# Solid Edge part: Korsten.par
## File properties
Author: Egon 815
Template: Normal.par
Last saved by: Egon 815
Revision: 5
Application: Solid Edge
Accuracy: 0,990
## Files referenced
..\Laev.asm
.C:\Kool\3D Modelleerimine\LaevaJoonis\Laev.asm
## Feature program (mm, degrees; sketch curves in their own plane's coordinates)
sketch for "unnamed Protrusion 1" plane through (0, 0, 8310) normal (0, 0, 1) x-axis (1, 0, 0)
  line (2766.1847, 955.2363) -> (2766.1847, -1432.5005)
  arc centre (854.3232, -1432.5005) radius 1911.8614 from (854.3232, -3344.362) to (2766.1847, -1432.5005) ccw
  line (854.3232, -3344.362) -> (-854.3232, -3344.362)
  arc centre (-854.3232, -1432.5005) radius 1911.8614 from (-2766.1847, -1432.5005) to (-854.3232, -3344.362) ccw
  line (-2766.1847, 955.2363) -> (-2766.1847, -1432.5005)
  arc centre (-854.3232, 955.2363) radius 1911.8614 from (-2766.1847, 955.2363) to (-854.3232, 2867.0978) cw
  line (-854.3232, 2867.0978) -> (854.3232, 2867.0978)
  arc centre (854.3232, 955.2363) radius 1911.8614 from (854.3232, 2867.0978) to (2766.1847, 955.2363) cw
extrude "unnamed Protrusion 1" add to key point along +normal
thinwall "unnamed Thinwall 1"
sketch for "unnamed Protrusion 2" plane through (0, -238.6321, 8310) normal (0, 0, -1) x-axis (0, 1, 0)
  line (238.6321, 6229.7809) -> (5327.3209, 6229.7809)
  line (5327.3209, 6229.7809) -> (5327.3209, -6074.0882)
  line (5327.3209, -6074.0882) -> (238.6321, -6074.0882)
  line (238.6321, -6074.0882) -> (238.6321, 6229.7809)
extrude "unnamed Protrusion 2" add to key point along -normal
sketch for "unnamed Protrusion 3" plane through (55.1803, 2544.3444, 11688.7578) normal (0, 0, 1) x-axis (0, 1, 0)
  line (-3976.8449, -4119.118) -> (911.1739, -4119.118)
  line (911.1739, -4119.118) -> (911.1739, 55.1803)
  line (911.1739, 4229.4786) -> (911.1739, 55.1803)
  line (-3976.8449, 4229.4786) -> (911.1739, 4229.4786)
  line (-3976.8449, 4229.4786) -> (-3976.8449, 55.1803)
  line (-3976.8449, -4119.118) -> (-3976.8449, 55.1803)
extrude "unnamed Protrusion 3" add to key point along +normal
chamfer "Chamfer_5" setback 200
fillet "Round_1" radius 1000
fillet "Round_3" radius 2000
fillet "Round_4" radius 1000
fillet "Round_5" radius 1000
sketch for "unnamed Protrusion 4" plane through (77.8463, 872.1634, 8310) normal (0, 0, -1) x-axis (1, 0, 0)
  line (-9245.1108, 5692.4091) -> (-6151.9346, 872.1634)
  line (-9245.1108, 5692.4091) -> (-77.8463, 5692.4091)
  line (9089.4181, 5692.4091) -> (-77.8463, 5692.4091)
  line (9089.4181, 5692.4091) -> (5996.2419, 872.1634)
  line (5996.2419, 872.1634) -> (-155.6927, 872.1634)
extrude "unnamed Protrusion 4" add to key point along -normal
fillet "Round_6" radius 500
chamfer "Chamfer_7" setback 200
chamfer "Chamfer_10" setback 200
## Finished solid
Body 1: solid body, 78 faces, 196 edges, 121 vertices.
  Faces by surface: plane 52, cylinder 18, torus 6, blend 2
  Edges by curve: line 140, circle 42, intersection 10, ellipse 4
Bounding box of the edges (mm; curved faces can reach further): 18334.529 x 9908.934 x 15550.165, from (-9167.2645, -4820.2457, 8310) to (9167.2645, 5088.6888, 23860.165).
Cylindrical faces by radius (mm): R500 x1, R1000 x7, R1851.8614 x4, R1911.8614 x4, R2000 x2
Toroidal faces (ring radius, tube radius in mm): R2411.8614 r500 x2, R2911.8614 r1000 x4
Planar faces by outward normal: +x 6, +y 4, +z 7, -x 6, -y 7, -z 4, oblique 18
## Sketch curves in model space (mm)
line (6074.0882, 0, 8310) -> (-77.8463, 0, 8310)
line (9167.2645, -4820.2457, 8310) -> (6074.0882, 0, 8310)
line (9167.2645, -4820.2457, 8310) -> (0, -4820.2457, 8310)
line (-9167.2645, -4820.2457, 8310) -> (0, -4820.2457, 8310)
line (-9167.2645, -4820.2457, 8310) -> (-6074.0882, 0, 8310)
line (-6074.0882, 0, 8310) -> (77.8463, 0, 8310)
line (-4174.2983, 3455.5183, 11688.7578) -> (0, 3455.5183, 11688.7578)
line (4174.2983, 3455.5183, 11688.7578) -> (0, 3455.5183, 11688.7578)
line (4174.2983, -1432.5005, 11688.7578) -> (4174.2983, 3455.5183, 11688.7578)
line (4174.2983, -1432.5005, 11688.7578) -> (0, -1432.5005, 11688.7578)
line (-4174.2983, -1432.5005, 11688.7578) -> (0, -1432.5005, 11688.7578)
line (-4174.2983, -1432.5005, 11688.7578) -> (-4174.2983, 3455.5183, 11688.7578)
line (6229.7809, 0, 8310) -> (6229.7809, 5088.6888, 8310)
line (6229.7809, 5088.6888, 8310) -> (-6074.0882, 5088.6888, 8310)
line (-6074.0882, 5088.6888, 8310) -> (-6074.0882, 0, 8310)
line (-6074.0882, 0, 8310) -> (6229.7809, 0, 8310)
line (-2766.1847, 955.2363, 8310) -> (-2766.1847, -1432.5005, 8310)
line (854.3232, -3344.362, 8310) -> (-854.3232, -3344.362, 8310)
line (-854.3232, 2867.0978, 8310) -> (854.3232, 2867.0978, 8310)
line (2766.1847, 955.2363, 8310) -> (2766.1847, -1432.5005, 8310)
arc centre (-854.3232, 955.2363, 8310) radius 1911.8614 from (-2766.1847, 955.2363, 8310) through (-2166.3221, 2345.8739, 8310) to (-854.3232, 2867.0978, 8310)
arc centre (854.3232, 955.2363, 8310) radius 1911.8614 from (854.3232, 2867.0978, 8310) through (2244.9608, 2267.2352, 8310) to (2766.1847, 955.2363, 8310)
arc centre (854.3232, -1432.5005, 8310) radius 1911.8614 from (854.3232, -3344.362, 8310) through (2244.9608, -2744.4995, 8310) to (2766.1847, -1432.5005, 8310)
arc centre (-854.3232, -1432.5005, 8310) radius 1911.8614 from (-2766.1847, -1432.5005, 8310) through (-2166.3221, -2823.1382, 8310) to (-854.3232, -3344.362, 8310)
line (-2766.1847, 955.2363, 8310) -> (-2766.1847, -1432.5005, 8310)
line (854.3232, -3344.362, 8310) -> (-854.3232, -3344.362, 8310)
line (-854.3232, 2867.0978, 8310) -> (854.3232, 2867.0978, 8310)
line (2766.1847, 955.2363, 8310) -> (2766.1847, -1432.5005, 8310)
arc centre (-854.3232, 955.2363, 8310) radius 1911.8614 from (-2766.1847, 955.2363, 8310) through (-2166.3221, 2345.8739, 8310) to (-854.3232, 2867.0978, 8310)
arc centre (854.3232, 955.2363, 8310) radius 1911.8614 from (854.3232, 2867.0978, 8310) through (2244.9608, 2267.2352, 8310) to (2766.1847, 955.2363, 8310)
arc centre (854.3232, -1432.5005, 8310) radius 1911.8614 from (854.3232, -3344.362, 8310) through (2244.9608, -2744.4995, 8310) to (2766.1847, -1432.5005, 8310)
arc centre (-854.3232, -1432.5005, 8310) radius 1911.8614 from (-2766.1847, -1432.5005, 8310) through (-2166.3221, -2823.1382, 8310) to (-854.3232, -3344.362, 8310)
line (-2893.7083, 1010.2748, 8310) -> (-2893.7083, -1487.539, 8310)
line (893.7083, -3487.539, 8310) -> (-893.7083, -3487.539, 8310)
line (-893.7083, 3010.2748, 8310) -> (893.7083, 3010.2748, 8310)
line (2893.7083, 1010.2748, 8310) -> (2893.7083, -1487.539, 8310)
arc centre (-893.7083, 1010.2748, 8310) radius 2000 from (-2893.7083, 1010.2748, 8310) through (-2266.1916, 2465.022, 8310) to (-893.7083, 3010.2748, 8310)
arc centre (893.7083, 1010.2748, 8310) radius 2000 from (893.7083, 3010.2748, 8310) through (2348.4556, 2382.758, 8310) to (2893.7083, 1010.2748, 8310)
arc centre (893.7083, -1487.539, 8310) radius 2000 from (893.7083, -3487.539, 8310) through (2348.4556, -2860.0223, 8310) to (2893.7083, -1487.539, 8310)
arc centre (-893.7083, -1487.539, 8310) radius 2000 from (-2893.7083, -1487.539, 8310) through (-2266.1916, -2942.2863, 8310) to (-893.7083, -3487.539, 8310)
line (-2893.7083, 1010.2748, 8310) -> (-2893.7083, -1487.539, 8310)
line (893.7083, -3487.539, 8310) -> (-893.7083, -3487.539, 8310)
line (-893.7083, 3010.2748, 8310) -> (893.7083, 3010.2748, 8310)
line (2893.7083, 1010.2748, 8310) -> (2893.7083, -1487.539, 8310)
arc centre (-893.7083, 1010.2748, 8310) radius 2000 from (-2893.7083, 1010.2748, 8310) through (-2266.1916, 2465.022, 8310) to (-893.7083, 3010.2748, 8310)
arc centre (893.7083, 1010.2748, 8310) radius 2000 from (893.7083, 3010.2748, 8310) through (2348.4556, 2382.758, 8310) to (2893.7083, 1010.2748, 8310)
arc centre (893.7083, -1487.539, 8310) radius 2000 from (893.7083, -3487.539, 8310) through (2348.4556, -2860.0223, 8310) to (2893.7083, -1487.539, 8310)
arc centre (-893.7083, -1487.539, 8310) radius 2000 from (-2893.7083, -1487.539, 8310) through (-2266.1916, -2942.2863, 8310) to (-893.7083, -3487.539, 8310)
line (0, 3037.3995, 23860.165) -> (0, 3037.3995, 8314.9532)
line (0, -4351.2813, 23860.165) -> (0, -4351.2813, 8314.9532)
line (0, -4351.2813, 23860.165) -> (0, 3037.3995, 23860.165)
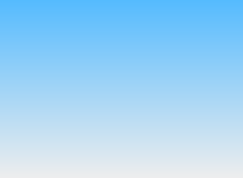
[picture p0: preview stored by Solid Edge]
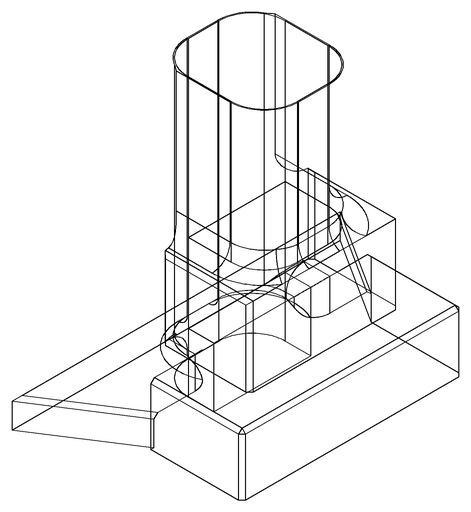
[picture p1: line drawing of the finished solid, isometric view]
